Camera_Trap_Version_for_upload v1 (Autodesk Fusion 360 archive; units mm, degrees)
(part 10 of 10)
sketch "Sketch1" plane through (0, 0, 0) normal (0, 0, 1) x axis (1, 0, 0)
  line L1 (5, 10) -> (-10, 10)
  line L2 (5, -25) -> (5, 10)
  line L3 (-10, -25) -> (5, -25)
  line L4 (-10, 10) -> (-10, -25)
  line L5 (-0.5549, -0.8) -> (-5, -0.8)
  line L6 (-2.7475, -3.1654) -> (-2.7475, 1.3967)
  line L7 (-4.495, -3.5) -> (-1, -3.5)
  line L8 (-5.495, 0.9) -> (-5.495, -2.5)
  line L9 (-1, 1.9) -> (-4.495, 1.9)
  line L10 (0, -2.5) -> (0, 0.9)
  line L11 (-5.495, 1.9) -> (0, -3.5)
  line L12 (0, 1.9) -> (-5.495, -3.5)
  line L13 (-2.7262, -15.3) -> (-2.7262, -10.8381)
  line L14 (-0.5, -13.0424) -> (-4.9528, -13.0424)
  line L15 (-2.7264, -13.0424) -> (-2.7475, -0.8)
  line L16 (7.263, -6.9039) -> (-2.7369, -6.9212)
  line L17 (-0.9696, -15.7363) -> (-4.4646, -15.7484)
  line L18 (-5.468, -14.7518) -> (-5.4797, -11.3519)
  line L19 (-4.4832, -10.3484) -> (-0.9882, -10.3363)
  line L20 (0.0152, -11.3329) -> (0.027, -14.7329)
  line L21 (1, -2.5) -> (1, 0.9)
  line L22 (-4.495, -4.5) -> (-1, -4.5)
  line L23 (-6.495, 0.9) -> (-6.495, -2.5)
  line L24 (-1, 2.9) -> (-4.495, 2.9)
  line L25 (-4.4867, -9.3484) -> (-0.9917, -9.3364)
  line L26 (-6.468, -14.7553) -> (-6.4797, -11.3553)
  line L27 (-0.9661, -16.7363) -> (-4.4611, -16.7484)
  line L28 (1.0152, -11.3294) -> (1.027, -14.7294)
  arc A1 centre (-4.495, 0.9) radius 1 clockwise from (-5.495, 0.9) to (-4.495, 1.9)
  arc A2 centre (-1, 0.9) radius 1 clockwise from (-1, 1.9) to (0, 0.9)
  arc A3 centre (-1, -2.5) radius 1 clockwise from (0, -2.5) to (-1, -3.5)
  arc A4 centre (-4.495, -2.5) radius 1 clockwise from (-4.495, -3.5) to (-5.495, -2.5)
  arc A5 centre (-4.4798, -11.3484) radius 1 clockwise from (-5.4797, -11.3519) to (-4.4832, -10.3484)
  arc A6 centre (-4.468, -14.7484) radius 1 clockwise from (-4.4646, -15.7484) to (-5.468, -14.7518)
  arc A7 centre (-0.973, -14.7363) radius 1 clockwise from (0.027, -14.7329) to (-0.9696, -15.7363)
  arc A8 centre (-0.9848, -11.3363) radius 1 clockwise from (-0.9882, -10.3363) to (0.0152, -11.3329)
  arc A9 centre (-1, -2.5) radius 2 clockwise from (1, -2.5) to (-1, -4.5)
  arc A10 centre (-4.495, -2.5) radius 2 clockwise from (-4.495, -4.5) to (-6.495, -2.5)
  arc A11 centre (-4.495, 0.9) radius 2 clockwise from (-6.495, 0.9) to (-4.495, 2.9)
  arc A12 centre (-1, 0.9) radius 2 clockwise from (-1, 2.9) to (1, 0.9)
  arc A13 centre (-4.4798, -11.3484) radius 2 clockwise from (-6.4797, -11.3553) to (-4.4867, -9.3484)
  arc A14 centre (-4.468, -14.7484) radius 2 clockwise from (-4.4611, -16.7484) to (-6.468, -14.7553)
  arc A15 centre (-0.973, -14.7363) radius 2 clockwise from (1.027, -14.7294) to (-0.9661, -16.7363)
  arc A16 centre (-0.9848, -11.3363) radius 2 clockwise from (-0.9917, -9.3364) to (1.0152, -11.3294)
  point P14 (-2.7475, -0.8)
  point P19 (-2.7475, -0.8)
  point P20 (-2.7264, -13.0424)
  point P21 (-2.7369, -6.9212)
  point P12 (-5.495, 1.9)
  point P13 (0, 1.9)
  point P10 (0, -3.5)
  point P11 (-5.495, -3.5)
  point P22 (7.263, -6.9039)
  horizontal L1
  perpendicular L1 L2
  perpendicular L2 L3
  perpendicular L1 L4
  horizontal L5
  perpendicular L5 L6
  horizontal L7
  perpendicular L7 L8
  parallel L7 L9
  parallel L8 L10
  coincident L11 P14
  coincident L12 P14
  coincident L5 P14
  coincident L6 P14
  vertical L13
  horizontal L14
  coincident P14 P19
  midpoint L14 P20
  midpoint L15 P21
  coincident P12 L8
  coincident P12 L9
  tangent L8 A1
  tangent L9 A1
  coincident P13 L9
  coincident P13 L10
  tangent L9 A2
  tangent L10 A2
  equal A1 A2
  coincident P10 L7
  coincident P10 L10
  tangent L7 A3
  tangent L10 A3
  equal A1 A3
  coincident P11 L7
  coincident P11 L8
  tangent L7 A4
  tangent L8 A4
  equal A1 A4
  tangent L19 A5
  tangent L18 A5
  equal A1 A5
  tangent L17 A6
  tangent L18 A6
  equal A1 A6
  tangent L17 A7
  tangent L20 A7
  equal A1 A7
  tangent L19 A8
  tangent L20 A8
  dimension "d14" angle L15 L16 = 90
  dimension "d15" distance P21 P22 = 10
  dimension "d18" radius A1 = 1
  dimension "d19" radius A8 = 1
  dimension "d22" distance A3 = 1
  dimension "d23" = 1
extrude "Extrude1" new body sketch "Sketch1" profile of L1 L2 L3 L4 L7 L8 L9 L10 L17 L18 L19 L20 A1 A2 A3 A4 A5 A6 A7 A8 L21 L22 L24 A12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 along normal blind 2 (= "Base_extrusion") taper -5 bodies "Base"
mesh_repair "MeshRepair1"
extrude "Extrude3" new body sketch "Sketch1" profile of L7 L8 L9 L10 L17 L18 L19 L20 A1 A2 A3 A4 A5 A6 A7 A8 A9 along normal blind 4 (= "button_extrusion") taper -5 bodies "Button_superior", "Button_inferior"
fillet "Fillet1" radius 0.5
fillet "Fillet2" radius 0.4
sketch "Sketch9" plane through (0, 0, 0) normal (1, 0, 0) x axis (0, 1, 0)
sketch "Sketch10" plane through (0, 0, 2) normal (0, 0, 1) x axis (-1, 0, 0)
  line L1 (9.825, 24.825) -> (9.825, -9.825)
  line L2 (-4.825, 24.825) -> (9.825, 24.825)
  line L3 (-4.825, -9.825) -> (-4.825, 24.825)
  line L4 (9.825, -9.825) -> (-4.825, -9.825)
  line L5 (1, 3.325) -> (4.495, 3.325)
  line L6 (0.175, -0.9) -> (0.175, 2.5)
  line L7 (4.495, -1.725) -> (1, -1.725)
  line L8 (5.32, 2.5) -> (5.32, -0.9)
  line L9 (0.1597, 11.3335) -> (0.148, 14.7335)
  line L10 (4.4826, 10.5234) -> (0.9876, 10.5113)
  line L11 (5.293, 14.7512) -> (5.3048, 11.3513)
  line L12 (0.9702, 15.5613) -> (4.4652, 15.5734)
  line L13 (6.293, 14.7547) -> (6.3048, 11.3547)
  line L14 (0.9667, 16.5613) -> (4.4617, 16.5734)
  line L15 (-0.8403, 11.33) -> (-0.852, 14.73)
  line L16 (4.486, 9.5234) -> (0.991, 9.5113)
  line L17 (4.495, -2.725) -> (1, -2.725)
  line L18 (6.32, 2.5) -> (6.32, -0.9)
  line L19 (1, 4.325) -> (4.495, 4.325)
  line L20 (-0.825, -0.9) -> (-0.825, 2.5)
  arc A1 centre (4.495, 2.5) radius 0.825 clockwise from (4.495, 3.325) to (5.32, 2.5)
  arc A2 centre (1, 2.5) radius 0.825 clockwise from (0.175, 2.5) to (1, 3.325)
  arc A3 centre (1, -0.9) radius 0.825 clockwise from (1, -1.725) to (0.175, -0.9)
  arc A4 centre (4.495, -0.9) radius 0.825 clockwise from (5.32, -0.9) to (4.495, -1.725)
  arc A5 centre (0.9848, 11.3363) radius 0.825 clockwise from (0.9876, 10.5113) to (0.1597, 11.3335)
  arc A6 centre (4.4798, 11.3484) radius 0.825 clockwise from (5.3048, 11.3513) to (4.4826, 10.5234)
  arc A7 centre (4.468, 14.7484) radius 0.825 clockwise from (4.4652, 15.5734) to (5.293, 14.7512)
  arc A8 centre (0.973, 14.7363) radius 0.825 clockwise from (0.148, 14.7335) to (0.9702, 15.5613)
  arc A9 centre (4.468, 14.7484) radius 1.825 clockwise from (4.4617, 16.5734) to (6.293, 14.7547)
  arc A10 centre (0.973, 14.7363) radius 1.825 clockwise from (-0.852, 14.73) to (0.9667, 16.5613)
  arc A11 centre (0.9848, 11.3363) radius 1.825 clockwise from (0.991, 9.5113) to (-0.8403, 11.33)
  arc A12 centre (4.4798, 11.3484) radius 1.825 clockwise from (6.3048, 11.3547) to (4.486, 9.5234)
  arc A13 centre (4.495, -0.9) radius 1.825 clockwise from (6.32, -0.9) to (4.495, -2.725)
  arc A14 centre (4.495, 2.5) radius 1.825 clockwise from (4.495, 4.325) to (6.32, 2.5)
  arc A15 centre (1, 2.5) radius 1.825 clockwise from (-0.825, 2.5) to (1, 4.325)
  arc A16 centre (1, -0.9) radius 1.825 clockwise from (1, -2.725) to (-0.825, -0.9)
  dimension "d33" = 1
  dimension "d34" = 1
extrude "Extrude6" cut sketch "Sketch10" profile of A1 L5 A2 L6 A3 L7 A4 L8 L9 A5 L10 A6 L11 A7 L12 A8 L14 A10 A9 L13 L16 L15 A11 A12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 against normal blind 1.9 taper -5
fillet "Fillet8" radius 0.43
fillet "Fillet9" radius 0.43
fillet "Fillet10" radius 1
fillet "Fillet11" radius 1
sketch "Wax_Block" plane through (0, 0, 0) normal (0, 0, 1) x axis (1, 0, 0)
  line L1 (15, 22) -> (-20, 22)
  line L2 (15, -68) -> (15, 22)
  line L3 (-20, -68) -> (15, -68)
  line L4 (-20, 22) -> (-20, -68)
  line L5 (-10, -25) -> (5, -25)
  line L6 (-10, 10) -> (-10, -25)
  line L7 (5, 10) -> (-10, 10)
  line L8 (5, -25) -> (5, 10)
  line L9 (7, -27) -> (7, 12)
  line L10 (-12, -27) -> (7, -27)
  line L11 (-12, 12) -> (-12, -27)
  line L12 (7, 12) -> (-12, 12)
  point P2 (-20, 22)
  point P3 (15, 22)
  point P5 (-20, -68)
  horizontal L1
  vertical L2
  horizontal L3
  vertical L4
  dimension "d55" distance P2 P3 = 35
  dimension "d56" distance P2 P5 = 90
  dimension "d63" = -2
fillet "Fillet12" radius 1
extrude "Extrude1" new body sketch "Wax_Block" profile of L1 L2 L3 L4 along normal blind 20 bodies "Wax_Block_Mold"
combine "Combine1"
extrude "Extrude2" add sketch "Wax_Block" profile of L1 L2 L3 L4 L11 L9 L10 L12 against normal blind 1
move "Move1"
move "Move2"
move "Move3"
move "Move4"
move "Move5"
position "Position1"
sketch "Sketch21" plane through (0, 0, 0) normal (0, 1, 0) x axis (1, 0, 0)
combine "Combine1" bodies "Base"
sketch "Sketch1" plane through (0, 0, 0) normal (0, 0, 1) x axis (1, 0, 0)
  line L1 (-4.495, -5.2382) -> (-1, -5.2382)
  curve K1 (-4.495, -5.2382) -> (-7.2332, -2.5)
  line L2 (-7.2332, 0.9) -> (-7.2332, -2.5)
  curve K2 (-7.2332, 0.9) -> (-4.495, 3.6382)
  line L3 (-1, 3.6382) -> (-4.495, 3.6382)
  curve K3 (-1, 3.6382) -> (1.7382, 0.9)
  line L4 (1.7382, -2.5) -> (1.7382, 0.9)
  curve K4 (1.7382, -2.5) -> (-1, -5.2382)
  line L5 (-4.4586, -17.4866) -> (-0.9636, -17.4745)
  curve K5 (-4.4586, -17.4866) -> (-7.2062, -14.7578)
  line L6 (-7.2179, -11.3579) -> (-7.2062, -14.7578)
  curve K6 (-7.2179, -11.3579) -> (-4.4892, -8.6102)
  line L7 (-0.9942, -8.5982) -> (-4.4892, -8.6102)
  curve K7 (-0.9942, -8.5982) -> (1.7534, -11.3269)
  line L8 (1.7652, -14.7269) -> (1.7534, -11.3269)
  curve K8 (1.7652, -14.7269) -> (-0.9636, -17.4745)
  line L9 (-8.9087, 8.9087) -> (3.9087, 8.9087)
  line L10 (-8.9087, -23.9087) -> (-8.9087, 8.9087)
  line L11 (3.9087, -23.9087) -> (-8.9087, -23.9087)
  line L12 (3.9087, 8.9087) -> (3.9087, -23.9087)
extrude "Extrude1" new body of existing geometry blind 2
move "Move1"
move "Move2"
component_insert "Component Insert1"
component_insert "Component Insert2"
component_insert "Component Insert3"
component_insert "Component Insert4"
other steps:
create_component "CreateComponent3"
create_component "CreateComponent4"
create_component "CreateComponent5"
create_component "CreateComponent6"
named bodies: "Base", "Button_superior", "Button_inferior", "Wax_Block_Mold"

design "1.3+Inch+OLED+Display"
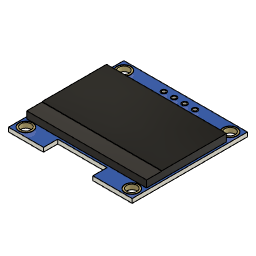
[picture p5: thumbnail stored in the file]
box_primitive "BoxPrimitive1" DistanceX 33.2 DistanceY 35.6 DistanceZ 1.2 OffsetDistanceX 0 OffsetDistanceY 0
sketch "Sketch2" plane through (0, 1.2, 0) normal (0, 1, 0) x axis (-1, 0, 0)
  line L1 (-35.6, 33.2) -> (0, 33.2)
  line L2 (-35.6, 0) -> (-35.6, 33.2)
  line L3 (0, 0) -> (-35.6, 0)
  line L4 (0, 33.2) -> (0, 0)
  line L5 (-24.2659, 33.2) -> (-10.0659, 33.2)
  line L6 (-24.2659, 29.1) -> (-24.2659, 33.2)
  line L7 (-10.0659, 29.1) -> (-24.2659, 29.1)
  line L8 (-10.0659, 33.2) -> (-10.0659, 29.1)
  point P6 (-10.0659, 33.2)
  point P7 (-24.2659, 33.2)
  point P9 (-10.0659, 29.1)
  horizontal L5
  vertical L6
  horizontal L7
  vertical L8
  coincident L1 P6
  dimension "d7" distance P6 P7 = 14.2
  dimension "d8" distance P6 P9 = 4.1
extrude "Extrude1" cut sketch "Sketch2" profile of L1 L5 L6 L7 L8 against normal blind 7
sketch "Sketch3" plane through (0, 1.2, 0) normal (0, 1, 0) x axis (-1, 0, 0)
  line L1 (-10.0659, 29.1) -> (-10.0659, 33.2)
  line L2 (-24.2659, 29.1) -> (-10.0659, 29.1)
  line L3 (-24.2659, 33.2) -> (-24.2659, 29.1)
  line L4 (-35.6, 33.2) -> (-24.2659, 33.2)
  line L5 (-35.6, 0) -> (-35.6, 33.2)
  line L6 (0, 0) -> (-35.6, 0)
  line L7 (0, 33.2) -> (0, 0)
  line L8 (-10.0659, 33.2) -> (0, 33.2)
  line L9 (-35.1, 22.762) -> (-35.6, 22.762)
  line L10 (-0.5394, 28.5002) -> (-35.0394, 28.5002)
  line L11 (-0.5394, 5.5002) -> (-0.5394, 28.5002)
  line L12 (-35.0394, 5.5002) -> (-0.5394, 5.5002)
  line L13 (-35.0394, 28.5002) -> (-35.0394, 5.5002)
  point P10 (-35.6, 22.762)
  point P11 (-35.1, 22.762)
  point P12 (-35.0394, 28.5002)
  point P13 (-0.5394, 28.5002)
  point P15 (-35.0394, 5.5002)
  coincident L5 P10
  perpendicular L5 L9
  horizontal L10
  vertical L11
  horizontal L12
  vertical L13
  dimension "d12" distance P10 P11 = 0.5
  dimension "d13" distance P12 P13 = 34.5
  dimension "d14" distance P12 P15 = 23
extrude "Extrude2" add sketch "Sketch3" profile of L10 L11 L12 L13 along normal blind 2.1
sketch "Sketch4" plane through (0, 1.2, 0) normal (0, 1, 0) x axis (-1, 0, 0)
  line L1 (-35.0394, 28.5002) -> (-35.0394, 5.5002)
  line L2 (-0.5394, 28.5002) -> (-35.0394, 28.5002)
  line L3 (-0.5394, 5.5002) -> (-0.5394, 28.5002)
  line L4 (-35.0394, 5.5002) -> (-0.5394, 5.5002)
  line L5 (-10.0659, 29.1) -> (-10.0659, 33.2)
  line L6 (-24.2659, 29.1) -> (-10.0659, 29.1)
  line L7 (-24.2659, 33.2) -> (-24.2659, 29.1)
  line L8 (-35.6, 33.2) -> (-24.2659, 33.2)
  line L9 (-35.6, 0) -> (-35.6, 33.2)
  line L10 (0, 0) -> (-35.6, 0)
  line L11 (0, 33.2) -> (0, 0)
  line L12 (-10.0659, 33.2) -> (0, 33.2)
  circle C1 centre (-2.5, 2.5) radius 1.5
  dimension "d17" diameter C1 = 3
extrude "Extrude3" cut sketch "Sketch4" profile of C1 against normal blind 12
sketch "Sketch5" plane through (0, 1.2, 0) normal (0, 1, 0) x axis (-1, 0, 0)
  line L1 (-35.0394, 28.5002) -> (-35.0394, 5.5002)
  line L2 (-0.5394, 28.5002) -> (-35.0394, 28.5002)
  line L3 (-0.5394, 5.5002) -> (-0.5394, 28.5002)
  line L4 (-35.0394, 5.5002) -> (-0.5394, 5.5002)
  line L5 (-10.0659, 29.1) -> (-10.0659, 33.2)
  line L6 (-24.2659, 29.1) -> (-10.0659, 29.1)
  line L7 (-24.2659, 33.2) -> (-24.2659, 29.1)
  line L8 (-35.6, 33.2) -> (-24.2659, 33.2)
  line L9 (-35.6, 0) -> (-35.6, 33.2)
  line L10 (0, 0) -> (-35.6, 0)
  line L11 (0, 33.2) -> (0, 0)
  line L12 (-10.0659, 33.2) -> (0, 33.2)
  circle C1 centre (-2.5, 2.5) radius 1.5
  circle C2 centre (-33.1, 2.5) radius 1.5
  dimension "d20" diameter C2 = 3
extrude "Extrude4" cut sketch "Sketch5" profile of C2 against normal blind 5
sketch "Sketch6" plane through (0, 1.2, 0) normal (0, 1, 0) x axis (-1, 0, 0)
  line L1 (-35.0394, 28.5002) -> (-35.0394, 5.5002)
  line L2 (-0.5394, 28.5002) -> (-35.0394, 28.5002)
  line L3 (-0.5394, 5.5002) -> (-0.5394, 28.5002)
  line L4 (-35.0394, 5.5002) -> (-0.5394, 5.5002)
  line L5 (-10.0659, 29.1) -> (-10.0659, 33.2)
  line L6 (-24.2659, 29.1) -> (-10.0659, 29.1)
  line L7 (-24.2659, 33.2) -> (-24.2659, 29.1)
  line L8 (-35.6, 33.2) -> (-24.2659, 33.2)
  line L9 (-35.6, 0) -> (-35.6, 33.2)
  line L10 (0, 0) -> (-35.6, 0)
  line L11 (0, 33.2) -> (0, 0)
  line L12 (-10.0659, 33.2) -> (0, 33.2)
  circle C1 centre (-33.1, 2.5) radius 1.5
  circle C2 centre (-2.5, 2.5) radius 1.5
  circle C3 centre (-2.5, 30.7) radius 1.5
  dimension "d23" diameter C3 = 3
extrude "Extrude5" cut sketch "Sketch6" profile of C3 against normal blind 2.6
sketch "Sketch7" plane through (0, 1.2, 0) normal (0, 1, 0) x axis (-1, 0, 0)
  line L1 (-35.0394, 28.5002) -> (-35.0394, 5.5002)
  line L2 (-0.5394, 28.5002) -> (-35.0394, 28.5002)
  line L3 (-0.5394, 5.5002) -> (-0.5394, 28.5002)
  line L4 (-35.0394, 5.5002) -> (-0.5394, 5.5002)
  line L5 (-10.0659, 29.1) -> (-10.0659, 33.2)
  line L6 (-24.2659, 29.1) -> (-10.0659, 29.1)
  line L7 (-24.2659, 33.2) -> (-24.2659, 29.1)
  line L8 (-35.6, 33.2) -> (-24.2659, 33.2)
  line L9 (-35.6, 0) -> (-35.6, 33.2)
  line L10 (0, 0) -> (-35.6, 0)
  line L11 (0, 33.2) -> (0, 0)
  line L12 (-10.0659, 33.2) -> (0, 33.2)
  circle C1 centre (-2.5, 30.7) radius 1.5
  circle C2 centre (-33.1, 2.5) radius 1.5
  circle C3 centre (-2.5, 2.5) radius 1.5
  circle C4 centre (-33.1, 30.8) radius 1.5
  dimension "d26" diameter C4 = 3
extrude "Extrude6" cut sketch "Sketch7" profile of C4 against normal blind 6
sketch "Sketch8" plane through (0, 1.2, 0) normal (0, 1, 0) x axis (-1, 0, 0)
  line L1 (-35.0394, 28.5002) -> (-35.0394, 5.5002)
  line L2 (-0.5394, 28.5002) -> (-35.0394, 28.5002)
  line L3 (-0.5394, 5.5002) -> (-0.5394, 28.5002)
  line L4 (-35.0394, 5.5002) -> (-0.5394, 5.5002)
  line L5 (-10.0659, 29.1) -> (-10.0659, 33.2)
  line L6 (-24.2659, 29.1) -> (-10.0659, 29.1)
  line L7 (-24.2659, 33.2) -> (-24.2659, 29.1)
  line L8 (-35.6, 33.2) -> (-24.2659, 33.2)
  line L9 (-35.6, 0) -> (-35.6, 33.2)
  line L10 (0, 0) -> (-35.6, 0)
  line L11 (0, 33.2) -> (0, 0)
  line L12 (-10.0659, 33.2) -> (0, 33.2)
  circle C1 centre (-33.1, 30.8) radius 1.5
  circle C2 centre (-2.5, 30.7) radius 1.5
  circle C3 centre (-33.1, 2.5) radius 1.5
  circle C4 centre (-2.5, 2.5) radius 1.5
  circle C5 centre (-2.5, 2.5) radius 2
  concentric C4 C5
  dimension "d29" diameter C5 = 4
extrude "Extrude7" add sketch "Sketch8" profile of C4 C5 along normal blind 0.1
sketch "Sketch9" plane through (0, 1.2, 0) normal (0, 1, 0) x axis (-1, 0, 0)
  line L1 (-35.0394, 28.5002) -> (-35.0394, 5.5002)
  line L2 (-0.5394, 28.5002) -> (-35.0394, 28.5002)
  line L3 (-0.5394, 5.5002) -> (-0.5394, 28.5002)
  line L4 (-35.0394, 5.5002) -> (-0.5394, 5.5002)
  line L5 (-10.0659, 29.1) -> (-10.0659, 33.2)
  line L6 (-24.2659, 29.1) -> (-10.0659, 29.1)
  line L7 (-24.2659, 33.2) -> (-24.2659, 29.1)
  line L8 (-35.6, 33.2) -> (-24.2659, 33.2)
  line L9 (-35.6, 0) -> (-35.6, 33.2)
  line L10 (0, 0) -> (-35.6, 0)
  line L11 (0, 33.2) -> (0, 0)
  line L12 (-10.0659, 33.2) -> (0, 33.2)
  circle C1 centre (-2.5, 2.5) radius 2
  circle C2 centre (-33.1, 30.8) radius 1.5
  circle C3 centre (-2.5, 30.7) radius 1.5
  circle C4 centre (-33.1, 2.5) radius 1.5
  circle C5 centre (-33.1, 2.5) radius 2
  concentric C4 C5
  dimension "d32" diameter C5 = 4
extrude "Extrude8" add sketch "Sketch9" profile of C4 C5 along normal blind 0.1
sketch "Sketch10" plane through (0, 1.2, 0) normal (0, 1, 0) x axis (-1, 0, 0)
  line L1 (-35.0394, 28.5002) -> (-35.0394, 5.5002)
  line L2 (-0.5394, 28.5002) -> (-35.0394, 28.5002)
  line L3 (-0.5394, 5.5002) -> (-0.5394, 28.5002)
  line L4 (-35.0394, 5.5002) -> (-0.5394, 5.5002)
  line L5 (-10.0659, 29.1) -> (-10.0659, 33.2)
  line L6 (-24.2659, 29.1) -> (-10.0659, 29.1)
  line L7 (-24.2659, 33.2) -> (-24.2659, 29.1)
  line L8 (-35.6, 33.2) -> (-24.2659, 33.2)
  line L9 (-35.6, 0) -> (-35.6, 33.2)
  line L10 (0, 0) -> (-35.6, 0)
  line L11 (0, 33.2) -> (0, 0)
  line L12 (-10.0659, 33.2) -> (0, 33.2)
  circle C1 centre (-33.1, 2.5) radius 2
  circle C2 centre (-2.5, 2.5) radius 2
  circle C3 centre (-33.1, 30.8) radius 1.5
  circle C4 centre (-2.5, 30.7) radius 1.5
  circle C5 centre (-33.1, 30.8) radius 2
  concentric C3 C5
  dimension "d35" diameter C5 = 4
extrude "Extrude9" add sketch "Sketch10" profile of C3 C5 along normal blind 0.1
sketch "Sketch11" plane through (0, 1.2, 0) normal (0, 1, 0) x axis (-1, 0, 0)
  line L1 (-35.0394, 28.5002) -> (-35.0394, 5.5002)
  line L2 (-0.5394, 28.5002) -> (-35.0394, 28.5002)
  line L3 (-0.5394, 5.5002) -> (-0.5394, 28.5002)
  line L4 (-35.0394, 5.5002) -> (-0.5394, 5.5002)
  line L5 (-10.0659, 29.1) -> (-10.0659, 33.2)
  line L6 (-24.2659, 29.1) -> (-10.0659, 29.1)
  line L7 (-24.2659, 33.2) -> (-24.2659, 29.1)
  line L8 (-35.6, 33.2) -> (-24.2659, 33.2)
  line L9 (-35.6, 0) -> (-35.6, 33.2)
  line L10 (0, 0) -> (-35.6, 0)
  line L11 (0, 33.2) -> (0, 0)
  line L12 (-10.0659, 33.2) -> (0, 33.2)
  circle C1 centre (-33.1, 30.8) radius 2
  circle C2 centre (-33.1, 2.5) radius 2
  circle C3 centre (-2.5, 2.5) radius 2
  circle C4 centre (-2.5, 30.7) radius 1.5
  circle C5 centre (-2.5, 30.7) radius 2
  concentric C4 C5
  dimension "d38" diameter C5 = 4
extrude "Extrude10" add sketch "Sketch11" profile of C4 C5 along normal blind 0.1
sketch "Sketch12" plane through (0, 0, 0) normal (0, -1, 0) x axis (1, 0, 0)
  line L1 (24.2659, 29.1) -> (24.2659, 33.2)
  line L2 (10.0659, 29.1) -> (24.2659, 29.1)
  line L3 (10.0659, 33.2) -> (10.0659, 29.1)
  line L4 (0, 33.2) -> (10.0659, 33.2)
  line L5 (0, 0) -> (0, 33.2)
  line L6 (35.6, 0) -> (0, 0)
  line L7 (35.6, 33.2) -> (35.6, 0)
  line L8 (24.2659, 33.2) -> (35.6, 33.2)
  circle C1 centre (33.1, 30.8) radius 1.5
  circle C2 centre (2.5, 30.7) radius 1.5
  circle C3 centre (33.1, 2.5) radius 1.5
  circle C4 centre (2.5, 2.5) radius 1.5
  circle C5 centre (33.1, 30.8) radius 2
  concentric C1 C5
  dimension "d41" diameter C5 = 4
extrude "Extrude11" add sketch "Sketch12" profile of C1 C5 along normal blind 0.1
sketch "Sketch13" plane through (0, 0, 0) normal (0, -1, 0) x axis (1, 0, 0)
  line L1 (24.2659, 29.1) -> (24.2659, 33.2)
  line L2 (10.0659, 29.1) -> (24.2659, 29.1)
  line L3 (10.0659, 33.2) -> (10.0659, 29.1)
  line L4 (0, 33.2) -> (10.0659, 33.2)
  line L5 (0, 0) -> (0, 33.2)
  line L6 (35.6, 0) -> (0, 0)
  line L7 (35.6, 33.2) -> (35.6, 0)
  line L8 (24.2659, 33.2) -> (35.6, 33.2)
  circle C1 centre (33.1, 30.8) radius 2
  circle C2 centre (2.5, 30.7) radius 1.5
  circle C3 centre (33.1, 2.5) radius 1.5
  circle C4 centre (2.5, 2.5) radius 1.5
  circle C5 centre (33.1, 2.5) radius 2
  concentric C3 C5
  dimension "d44" diameter C5 = 4
extrude "Extrude12" add sketch "Sketch13" profile of C3 C5 along normal blind 0.1
sketch "Sketch14" plane through (0, 0, 0) normal (0, -1, 0) x axis (1, 0, 0)
  line L1 (24.2659, 29.1) -> (24.2659, 33.2)
  line L2 (10.0659, 29.1) -> (24.2659, 29.1)
  line L3 (10.0659, 33.2) -> (10.0659, 29.1)
  line L4 (0, 33.2) -> (10.0659, 33.2)
  line L5 (0, 0) -> (0, 33.2)
  line L6 (35.6, 0) -> (0, 0)
  line L7 (35.6, 33.2) -> (35.6, 0)
  line L8 (24.2659, 33.2) -> (35.6, 33.2)
  circle C1 centre (33.1, 2.5) radius 2
  circle C2 centre (33.1, 30.8) radius 2
  circle C3 centre (2.5, 30.7) radius 1.5
  circle C4 centre (2.5, 2.5) radius 1.5
  circle C5 centre (2.5, 2.5) radius 2
  concentric C4 C5
  dimension "d47" diameter C5 = 4
extrude "Extrude13" add sketch "Sketch14" profile of C4 C5 along normal blind 0.1
sketch "Sketch15" plane through (0, 0, 0) normal (0, -1, 0) x axis (1, 0, 0)
  line L1 (24.2659, 29.1) -> (24.2659, 33.2)
  line L2 (10.0659, 29.1) -> (24.2659, 29.1)
  line L3 (10.0659, 33.2) -> (10.0659, 29.1)
  line L4 (0, 33.2) -> (10.0659, 33.2)
  line L5 (0, 0) -> (0, 33.2)
  line L6 (35.6, 0) -> (0, 0)
  line L7 (35.6, 33.2) -> (35.6, 0)
  line L8 (24.2659, 33.2) -> (35.6, 33.2)
  circle C1 centre (2.5, 2.5) radius 2
  circle C2 centre (33.1, 2.5) radius 2
  circle C3 centre (33.1, 30.8) radius 2
  circle C4 centre (2.5, 30.7) radius 1.5
  circle C5 centre (2.5, 30.7) radius 2
  concentric C4 C5
  dimension "d50" diameter C5 = 4
extrude "Extrude14" add sketch "Sketch15" profile of C4 C5 along normal blind 0.1
sketch "Sketch16" plane through (0, 1.2, 0) normal (0, 1, 0) x axis (-1, 0, 0)
  line L1 (-35.0394, 28.5002) -> (-35.0394, 5.5002)
  line L2 (-0.5394, 28.5002) -> (-35.0394, 28.5002)
  line L3 (-0.5394, 5.5002) -> (-0.5394, 28.5002)
  line L4 (-35.0394, 5.5002) -> (-0.5394, 5.5002)
  line L5 (-10.0659, 29.1) -> (-10.0659, 33.2)
  line L6 (-24.2659, 29.1) -> (-10.0659, 29.1)
  line L7 (-24.2659, 33.2) -> (-24.2659, 29.1)
  line L8 (-35.6, 33.2) -> (-24.2659, 33.2)
  line L9 (-35.6, 0) -> (-35.6, 33.2)
  line L10 (0, 0) -> (-35.6, 0)
  line L11 (0, 33.2) -> (0, 0)
  line L12 (-10.0659, 33.2) -> (0, 33.2)
  circle C1 centre (-2.5, 30.7) radius 2
  circle C2 centre (-33.1, 30.8) radius 2
  circle C3 centre (-33.1, 2.5) radius 2
  circle C4 centre (-2.5, 2.5) radius 2
  circle C5 centre (-16.5, 2) radius 0.5
  circle C6 centre (-19.5, 2) radius 0.5
  circle C7 centre (-13.5, 2) radius 0.5
  circle C8 centre (-22.5, 2) radius 0.5
  point P18 (-16.5, 2)
  point P20 (-13.5, 2)
  point P19 (-19.5, 2)
  point P21 (-22.5, 2)
  dimension "d55" diameter C5 = 1
  dimension "d56" diameter C6 = 1
  dimension "d57" distance P18 P20 = 3
  dimension "d58" diameter C7 = 1
  dimension "d59" distance P19 P21 = 3
  dimension "d60" diameter C8 = 1
extrude "Extrude15" cut sketch "Sketch16" profile of C5 C6 C7 C8 against normal blind 2.7
sketch "Sketch17" plane through (0, 1.2, 0) normal (0, 1, 0) x axis (-1, 0, 0)
  line L1 (-35.0394, 28.5002) -> (-35.0394, 5.5002)
  line L2 (-0.5394, 28.5002) -> (-35.0394, 28.5002)
  line L3 (-0.5394, 5.5002) -> (-0.5394, 28.5002)
  line L4 (-35.0394, 5.5002) -> (-0.5394, 5.5002)
  line L5 (-10.0659, 29.1) -> (-10.0659, 33.2)
  line L6 (-24.2659, 29.1) -> (-10.0659, 29.1)
  line L7 (-24.2659, 33.2) -> (-24.2659, 29.1)
  line L8 (-35.6, 33.2) -> (-24.2659, 33.2)
  line L9 (-35.6, 0) -> (-35.6, 33.2)
  line L10 (0, 0) -> (-35.6, 0)
  line L11 (0, 33.2) -> (0, 0)
  line L12 (-10.0659, 33.2) -> (0, 33.2)
  circle C1 centre (-19.5, 2) radius 0.5
  circle C2 centre (-16.5, 2) radius 0.5
  circle C3 centre (-22.5, 2) radius 0.5
  circle C4 centre (-13.5, 2) radius 0.5
  circle C5 centre (-2.5, 30.7) radius 2
  circle C6 centre (-33.1, 30.8) radius 2
  circle C7 centre (-33.1, 2.5) radius 2
  circle C8 centre (-2.5, 2.5) radius 2
  circle C9 centre (-13.5, 2) radius 0.75
  circle C10 centre (-16.5, 2) radius 0.75
  circle C11 centre (-19.5, 2) radius 0.75
  circle C12 centre (-22.5, 2) radius 0.75
  concentric C4 C9
  concentric C2 C10
  concentric C1 C11
  concentric C3 C12
  dimension "d63" diameter C9 = 1.5
  dimension "d64" diameter C10 = 1.5
  dimension "d65" diameter C11 = 1.5
  dimension "d66" diameter C12 = 1.5
extrude "Extrude16" add sketch "Sketch17" profile of C1 C2 C3 C4 C9 C10 C11 C12 along normal blind 0.1
extrude "Extrude17" cut of existing geometry blind -0.05
sketch "Sketch18" plane through (0, 0, 0) normal (0, -1, 0) x axis (1, 0, 0)
  line L1 (24.2659, 29.1) -> (24.2659, 33.2)
  line L2 (10.0659, 29.1) -> (24.2659, 29.1)
  line L3 (10.0659, 33.2) -> (10.0659, 29.1)
  line L4 (0, 33.2) -> (10.0659, 33.2)
  line L5 (0, 0) -> (0, 33.2)
  line L6 (35.6, 0) -> (0, 0)
  line L7 (35.6, 33.2) -> (35.6, 0)
  line L8 (24.2659, 33.2) -> (35.6, 33.2)
  circle C1 centre (19.5, 2) radius 0.5
  circle C2 centre (16.5, 2) radius 0.5
  circle C3 centre (22.5, 2) radius 0.5
  circle C4 centre (13.5, 2) radius 0.5
  circle C5 centre (2.5, 30.7) radius 2
  circle C6 centre (2.5, 2.5) radius 2
  circle C7 centre (33.1, 2.5) radius 2
  circle C8 centre (33.1, 30.8) radius 2
  circle C9 centre (13.5, 2) radius 0.75
  circle C10 centre (16.5, 2) radius 0.75
  circle C11 centre (19.5, 2) radius 0.75
  circle C12 centre (22.5, 2) radius 0.75
  concentric C4 C9
  concentric C2 C10
  concentric C1 C11
  concentric C3 C12
  dimension "d71" diameter C9 = 1.5
  dimension "d72" diameter C10 = 1.5
  dimension "d73" diameter C11 = 1.5
  dimension "d74" diameter C12 = 1.5
extrude "Extrude18" add sketch "Sketch18" profile of C1 C2 C3 C4 C9 C10 C11 C12 along normal blind 0.05
sketch "Sketch19" plane through (0, 3.3, 0) normal (0, 1, 0) x axis (-1, 0, 0)
  line L1 (-0.5394, 5.5002) -> (-35.0394, 5.5002)
  line L2 (-0.5394, 28.5002) -> (-0.5394, 5.5002)
  line L3 (-35.0394, 28.5002) -> (-0.5394, 28.5002)
  line L4 (-35.0394, 5.5002) -> (-35.0394, 28.5002)
  line L5 (-35.051, 28.5002) -> (-0.5394, 28.5002)
  line L6 (-35.051, 24.1002) -> (-35.051, 28.5002)
  line L7 (-0.5394, 24.1002) -> (-35.051, 24.1002)
  line L8 (-0.5394, 28.5002) -> (-0.5394, 24.1002)
  point P4 (-0.5394, 28.5002)
  point P6 (-0.5394, 28.5002)
  point P9 (-0.5394, 24.1002)
  horizontal L5
  vertical L6
  horizontal L7
  vertical L8
  coincident P4 P6
  dimension "d77" distance P6 P9 = 4.4
extrude "Extrude19" cut sketch "Sketch19" profile of L2 L3 L4 L5 L7 L8 against normal blind 0.1
component_from_bodies "Body->Comp"
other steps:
base_feature "Base Feature"
create_component "CreateComponent1"
remove_body "RemoveBody1"

design "9Vcell"
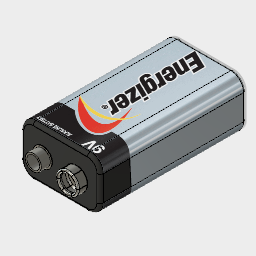
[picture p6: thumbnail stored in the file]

design "Button_Board_II"
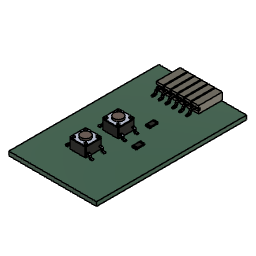
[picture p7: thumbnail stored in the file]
description: KiCad electronic assembly
part number: Button_Board_II 1
description: Part Number
part number: Ceramic
part number: Contacts
part number: Contacts (Mirror #1)
part number: Overcoat
part number: Resistor-1206
part number: Body
part number: Body001
part number: Body002
part number: Body003 (Mirror #1)
base_feature "Base Feature1"
base_feature "Base Feature1"
base_feature "Base Feature1"
base_feature "Base Feature1"
base_feature "Base Feature1"
base_feature "Base Feature1"
base_feature "Base Feature1"
base_feature "Base Feature1"
base_feature "Base Feature1"
base_feature "Base Feature1"
base_feature "Base Feature1"
base_feature "Base Feature1"
base_feature "Base Feature1"
base_feature "Base Feature1"
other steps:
create_component "CreateComponent1"
create_component "CreateComponent1"
create_component "CreateComponent2"
create_component "CreateComponent3"
create_component "CreateComponent4"
create_component "CreateComponent2"
create_component "CreateComponent1"
create_component "CreateComponent2"
create_component "CreateComponent3"
create_component "CreateComponent4"
create_component "CreateComponent5"
create_component "CreateComponent6"
create_component "CreateComponent7"
create_component "CreateComponent3"
create_component "CreateComponent1"
create_component "CreateComponent2"
create_component "CreateComponent4"

design "DB_Updated"
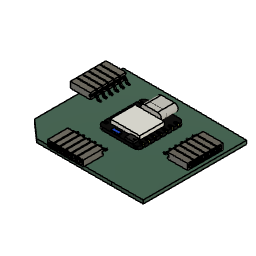
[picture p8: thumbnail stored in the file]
description: KiCad electronic assembly
part number: DB_Updated 1
description: Part Number
part number: DB_Updated 1.1.1
part number: DB_Updated 1.1.2
part number: PinSocket-01x06_P2.54mm_Horizontal_SMD
part number: SoC_nRF_Sense
part number: Mic_nRF_Sense
part number: Antenna_nRF_Sense
part number: Board
part number: USB
part number: Contact
base_feature "Base Feature1"
base_feature "Base Feature1"
base_feature "Base Feature1"
base_feature "Base Feature1"
base_feature "Base Feature1"
base_feature "Base Feature1"
base_feature "Base Feature1"
base_feature "Base Feature1"
base_feature "Base Feature1"
base_feature "Base Feature1"
base_feature "Base Feature1"
base_feature "Base Feature1"
base_feature "Base Feature1"
base_feature "Base Feature1"
base_feature "Base Feature1"
base_feature "Base Feature1"
base_feature "Base Feature1"
base_feature "Base Feature1"
base_feature "Base Feature1"
base_feature "Base Feature1"
base_feature "Base Feature1"
base_feature "Base Feature1"
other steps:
create_component "CreateComponent1"
create_component "CreateComponent1"
create_component "CreateComponent2"
create_component "CreateComponent2"
create_component "CreateComponent1"
create_component "CreateComponent2"
create_component "CreateComponent3"
create_component "CreateComponent4"
create_component "CreateComponent1"
create_component "CreateComponent2"
create_component "CreateComponent3"
create_component "CreateComponent4"
create_component "CreateComponent1"
create_component "CreateComponent2"
create_component "CreateComponent3"
create_component "CreateComponent4"
create_component "CreateComponent5"
create_component "CreateComponent6"
create_component "CreateComponent7"
create_component "CreateComponent8"
create_component "CreateComponent9"
create_component "CreateComponent10"
create_component "CreateComponent11"
create_component "CreateComponent12"
create_component "CreateComponent13"
create_component "CreateComponent3"

design "Half_Bridge"
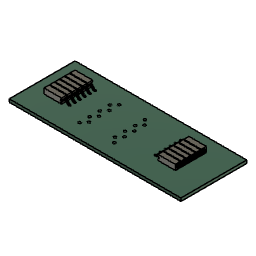
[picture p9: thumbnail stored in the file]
description: KiCad electronic assembly
part number: Half_Bridge 1
description: Part Number
part number: Half_Bridge 1.1.1
part number: Half_Bridge 1.1.2
part number: PinSocket-01x06_P2.54mm_Horizontal_SMD
part number: Half_Bridge_PCB
base_feature "Base Feature1"
base_feature "Base Feature1"
base_feature "Base Feature1"
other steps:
create_component "CreateComponent1"
create_component "CreateComponent1"
create_component "CreateComponent2"
create_component "CreateComponent2"

design "Half_Bridge"
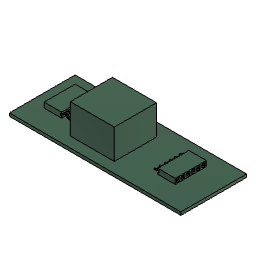
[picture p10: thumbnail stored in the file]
description: KiCad electronic assembly
part number: Half_Bridge 1
description: Part Number
part number: Half_Bridge 1.1.1
part number: Half_Bridge 1.1.2
part number: PinSocket-01x06_P2.54mm_Horizontal_SMD
part number: Half_Bridge_PCB
base_feature "Base Feature1"
base_feature "Base Feature1"
base_feature "Base Feature1"
combine "Combine1"
sketch "Sketch1" plane through (0, 0, 1.51) normal (0, 0, 1) x axis (-1, 0, 0)
  line L1 (-203.14, 113.4) -> (-116.66, 113.4)
  line L2 (-203.14, 80.27) -> (-203.14, 113.4)
  line L3 (-116.66, 80.27) -> (-203.14, 80.27)
  line L4 (-116.66, 113.4) -> (-116.66, 80.27)
  line L5 (-164.3124, 86.87) -> (-142.0898, 86.87)
  line L6 (-164.3124, 108.1498) -> (-164.3124, 86.87)
  line L7 (-142.0898, 108.1498) -> (-164.3124, 108.1498)
  line L8 (-142.0898, 86.87) -> (-142.0898, 108.1498)
  circle C1 centre (-144.7432, 106.03) radius 0.66
  circle C2 centre (-146.9276, 103.49) radius 0.66
  circle C3 centre (-144.6924, 100.95) radius 0.66
  circle C4 centre (-146.8768, 98.41) radius 0.66
  circle C5 centre (-162.2692, 106.03) radius 0.66
  circle C6 centre (-160.034, 103.49) radius 0.66
  circle C7 centre (-162.2692, 100.95) radius 0.66
  circle C8 centre (-159.9832, 98.41) radius 0.66
  circle C9 centre (-144.6924, 95.87) radius 0.66
  circle C10 centre (-146.9276, 93.2792) radius 0.66
  circle C11 centre (-144.6924, 90.7392) radius 0.66
  circle C12 centre (-146.9276, 88.3516) radius 0.66
  circle C13 centre (-162.1676, 95.87) radius 0.66
  circle C14 centre (-160.034, 93.3808) radius 0.66
  circle C15 centre (-162.1676, 90.79) radius 0.66
  circle C16 centre (-159.9324, 88.4024) radius 0.66
  horizontal L5
  vertical L6
  horizontal L7
  vertical L8
extrude "Extrude1" add sketch "Sketch1" profile of C1 C2 C3 C4 C5 C6 C7 C8 C9 C10 C11 C12 C13 C14 C15 C16 L5 L6 L7 L8 along normal blind 15
combine "Combine1"
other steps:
create_component "CreateComponent1"
create_component "CreateComponent1"
create_component "CreateComponent2"
create_component "CreateComponent2"
create_component "CreateComponent3"
create_component "CreateComponent1"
